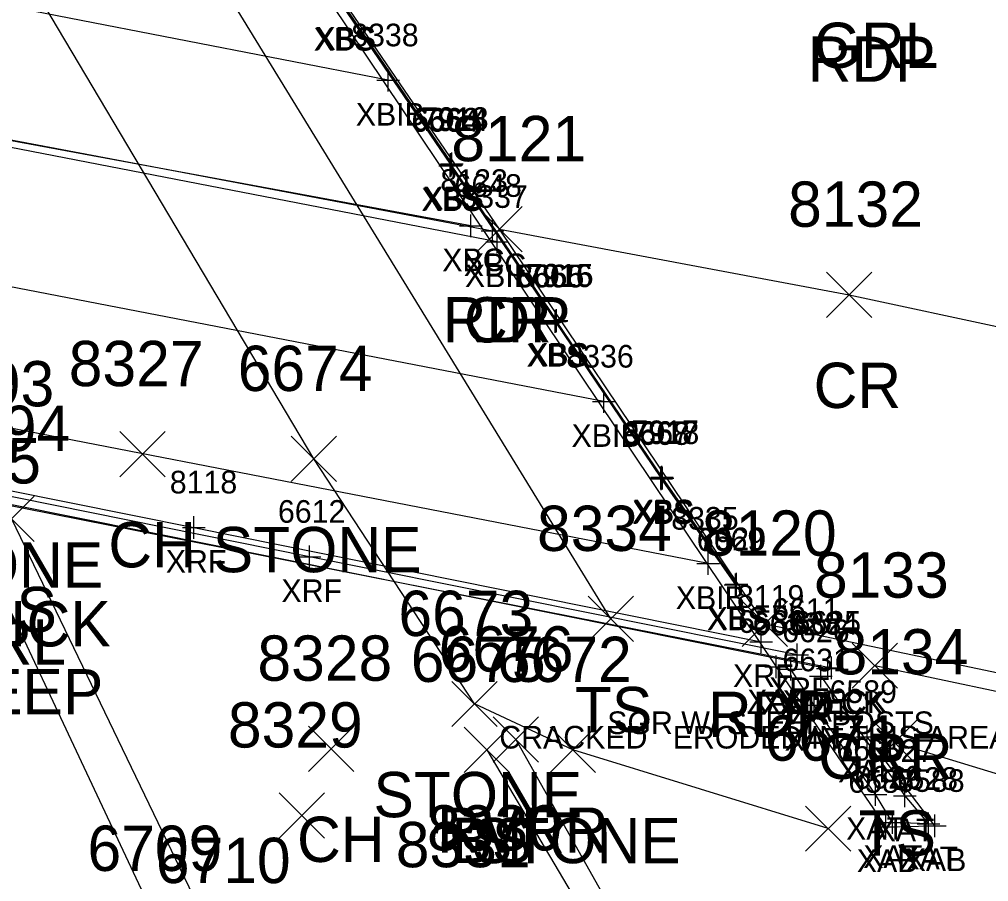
# Model space of a CAD drawing. Extents: x 1588028 to 1589597, y 137576 to 138176.
# Drawn here: x 1588943.52 to 1588986.3, y 137826.6 to 137864.66 of the extents above; entities that cross this region are included whole.
import ezdxf

# ---------------------------------------------------------------- set-up
doc = ezdxf.new("R2010")
doc.units = 0
for name, color, linetype in [('B_A', 7, 'Continuous'), ('B_C', 7, 'Continuous'), ('B_I', 7, 'Continuous'), ('B_TIC', 7, 'Continuous'), ('BB', 7, 'Continuous'), ('BELB', 7, 'Continuous'), ('BR', 7, 'Continuous'), ('BSE', 7, 'Continuous'), ('BSUBM', 7, 'Continuous'), ('L_A', 7, 'Continuous'), ('L_C', 7, 'Continuous'), ('L_I', 7, 'Continuous'), ('L_TIC', 7, 'Continuous'), ('LASF', 7, 'Continuous'), ('LAWE', 7, 'Continuous'), ('LELB', 7, 'Continuous'), ('P_A', 7, 'Continuous'), ('P_I', 7, 'Continuous'), ('P_TIC', 7, 'Continuous'), ('PET', 7, 'Continuous'), ('PRC', 7, 'Continuous'), ('R_A', 7, 'Continuous'), ('R_I', 7, 'Continuous'), ('R_TIC', 7, 'Continuous'), ('RGR', 7, 'Continuous')]:
    doc.layers.add(name, color=color, linetype=linetype)

msp = doc.modelspace()

# ---------------------------------------------------------------- linework, layer by layer
at = {"layer": 'B_TIC'}
for p, q in [((1588959.802, 137861.973), (1588959.878, 137861.973)), ((1588962.532, 137858.2), (1588962.608, 137858.2)), ((1588962.557, 137858.252), (1588962.633, 137858.252)), ((1588962.582, 137858.229), (1588962.657, 137858.229)), ((1588962.607, 137858.282), (1588962.683, 137858.282)), ((1588963.455, 137855.546), (1588963.53, 137855.546)), ((1588964.405, 137855.327), (1588964.481, 137855.327)), ((1588964.619, 137854.84), (1588964.694, 137854.84)), ((1588967.166, 137851.326), (1588967.241, 137851.326)), ((1588967.185, 137851.34), (1588967.261, 137851.34)), ((1588967.223, 137851.341), (1588967.299, 137851.341)), ((1588967.239, 137851.37), (1588967.314, 137851.37)), ((1588969.324, 137847.789), (1588969.4, 137847.789)), ((1588971.842, 137844.422), (1588971.917, 137844.422)), ((1588971.844, 137844.377), (1588971.92, 137844.377)), ((1588971.887, 137844.455), (1588971.963, 137844.455)), ((1588971.904, 137844.414), (1588971.98, 137844.414)), ((1588951.228, 137842.233), (1588951.304, 137842.233)), ((1588956.332, 137840.938), (1588956.408, 137840.938)), ((1588973.925, 137840.635), (1588974, 137840.635)), ((1588975.13, 137839.692), (1588975.205, 137839.692)), ((1588975.171, 137839.727), (1588975.246, 137839.727)), ((1588976.26, 137837.185), (1588976.336, 137837.185)), ((1588977.856, 137836.609), (1588977.931, 137836.609)), ((1588976.925, 137836.077), (1588977, 137836.077)), ((1588977.569, 137835.971), (1588977.645, 137835.971)), ((1588979.206, 137836), (1588979.281, 137836)), ((1588979.375, 137836.039), (1588979.45, 137836.039)), ((1588978.895, 137835.664), (1588978.97, 137835.664)), ((1588978.599, 137834.382), (1588978.675, 137834.382)), ((1588980.939, 137832.981), (1588981.014, 137832.981)), ((1588981.306, 137830.441), (1588981.382, 137830.441)), ((1588982.608, 137830.379), (1588982.683, 137830.379)), ((1588981.765, 137829.017), (1588981.841, 137829.017)), ((1588982.067, 137829.203), (1588982.142, 137829.203)), ((1588983.653, 137829.145), (1588983.729, 137829.145)), ((1588983.922, 137829.058), (1588983.998, 137829.058))]:
    msp.add_line(p, q, dxfattribs=at)
for points in [[(1588959.799, 137861.473), (1588959.799, 137862.473)], [(1588959.299, 137861.973), (1588960.299, 137861.973)], [(1588962.529, 137857.7), (1588962.529, 137858.7)], [(1588962.554, 137857.752), (1588962.554, 137858.752)], [(1588962.578, 137857.729), (1588962.578, 137858.729)], [(1588962.604, 137857.782), (1588962.604, 137858.782)], [(1588962.029, 137858.2), (1588963.029, 137858.2)], [(1588962.054, 137858.252), (1588963.054, 137858.252)], [(1588962.078, 137858.229), (1588963.078, 137858.229)], [(1588962.104, 137858.282), (1588963.104, 137858.282)], [(1588963.452, 137855.046), (1588963.452, 137856.046)], [(1588962.952, 137855.546), (1588963.952, 137855.546)], [(1588964.402, 137854.827), (1588964.402, 137855.827)], [(1588963.902, 137855.327), (1588964.902, 137855.327)], [(1588964.615, 137854.34), (1588964.615, 137855.34)], [(1588964.115, 137854.84), (1588965.115, 137854.84)], [(1588967.162, 137850.826), (1588967.162, 137851.826)], [(1588967.182, 137850.84), (1588967.182, 137851.84)], [(1588967.22, 137850.841), (1588967.22, 137851.841)], [(1588967.235, 137850.87), (1588967.235, 137851.87)], [(1588966.662, 137851.326), (1588967.662, 137851.326)], [(1588966.682, 137851.34), (1588967.682, 137851.34)], [(1588966.72, 137851.341), (1588967.72, 137851.341)], [(1588966.735, 137851.37), (1588967.735, 137851.37)], [(1588969.321, 137847.289), (1588969.321, 137848.289)], [(1588968.821, 137847.789), (1588969.821, 137847.789)], [(1588971.838, 137843.922), (1588971.838, 137844.922)], [(1588971.841, 137843.877), (1588971.841, 137844.877)], [(1588971.884, 137843.955), (1588971.884, 137844.955)], [(1588971.901, 137843.914), (1588971.901, 137844.914)], [(1588971.338, 137844.422), (1588972.338, 137844.422)], [(1588971.341, 137844.377), (1588972.341, 137844.377)], [(1588971.384, 137844.455), (1588972.384, 137844.455)], [(1588971.401, 137844.414), (1588972.401, 137844.414)], [(1588951.225, 137841.733), (1588951.225, 137842.733)], [(1588950.725, 137842.233), (1588951.725, 137842.233)], [(1588956.329, 137840.438), (1588956.329, 137841.438)], [(1588955.829, 137840.938), (1588956.829, 137840.938)], [(1588973.921, 137840.135), (1588973.921, 137841.135)], [(1588973.421, 137840.635), (1588974.421, 137840.635)], [(1588975.126, 137839.192), (1588975.126, 137840.192)], [(1588975.167, 137839.227), (1588975.167, 137840.227)], [(1588974.626, 137839.692), (1588975.626, 137839.692)], [(1588974.667, 137839.727), (1588975.667, 137839.727)], [(1588976.257, 137836.685), (1588976.257, 137837.685)], [(1588975.757, 137837.185), (1588976.757, 137837.185)], [(1588977.852, 137836.109), (1588977.852, 137837.109)], [(1588977.352, 137836.609), (1588978.352, 137836.609)], [(1588976.922, 137835.577), (1588976.922, 137836.577)], [(1588977.566, 137835.471), (1588977.566, 137836.471)], [(1588978.891, 137835.164), (1588978.891, 137836.164)], [(1588979.202, 137835.5), (1588979.202, 137836.5)], [(1588979.371, 137835.539), (1588979.371, 137836.539)], [(1588976.422, 137836.077), (1588977.422, 137836.077)], [(1588977.066, 137835.971), (1588978.066, 137835.971)], [(1588978.702, 137836), (1588979.702, 137836)], [(1588978.871, 137836.039), (1588979.871, 137836.039)], [(1588978.391, 137835.664), (1588979.391, 137835.664)], [(1588978.596, 137833.882), (1588978.596, 137834.882)], [(1588978.096, 137834.382), (1588979.096, 137834.382)], [(1588980.935, 137832.481), (1588980.935, 137833.481)], [(1588980.435, 137832.981), (1588981.435, 137832.981)], [(1588981.303, 137829.941), (1588981.303, 137830.941)], [(1588982.604, 137829.879), (1588982.604, 137830.879)], [(1588980.803, 137830.441), (1588981.803, 137830.441)], [(1588982.104, 137830.379), (1588983.104, 137830.379)], [(1588981.762, 137828.517), (1588981.762, 137829.517)], [(1588982.063, 137828.703), (1588982.063, 137829.703)], [(1588983.65, 137828.645), (1588983.65, 137829.645)], [(1588983.919, 137828.558), (1588983.919, 137829.558)], [(1588981.262, 137829.017), (1588982.262, 137829.017)], [(1588981.563, 137829.203), (1588982.563, 137829.203)], [(1588983.15, 137829.145), (1588984.15, 137829.145)], [(1588983.419, 137829.058), (1588984.419, 137829.058)]]:
    msp.add_lwpolyline(points, dxfattribs=at)
at = {"layer": 'BB'}
for points in [[(1588959.799, 137861.973), (1588912.85, 137871.124)], [(1588964.615, 137854.84), (1588917.658, 137863.951)], [(1588969.321, 137847.789), (1588922.415, 137856.857)], [(1588973.921, 137840.635), (1588927.197, 137849.709)]]:
    msp.add_lwpolyline(points, dxfattribs=at)
at = {"layer": 'BELB'}
for points in [[(1588917.303, 137864.223), (1588964.402, 137855.327)], [(1588963.452, 137855.546), (1588941.811, 137859.552), (1588919.044, 137863.553)], [(1588927.114, 137846.372), (1588979.371, 137836.039)], [(1588928.029, 137846.292), (1588979.202, 137836)]]:
    msp.add_lwpolyline(points, dxfattribs=at)
at = {"layer": 'BR'}
for points in [[(1588977.852, 137836.609), (1588956.329, 137840.938), (1588928.977, 137846.459)], [(1588929.192, 137846.665), (1588951.225, 137842.233), (1588976.257, 137837.185)]]:
    msp.add_lwpolyline(points, dxfattribs=at)
at = {"layer": 'BSE'}
for points in [[(1588954.828, 137869.716), (1588957.8, 137865.297), (1588957.774, 137865.279), (1588962.554, 137858.252), (1588962.529, 137858.2), (1588967.182, 137851.34), (1588967.162, 137851.326), (1588971.838, 137844.422), (1588971.841, 137844.377), (1588975.126, 137839.692)], [(1588954.879, 137869.737), (1588957.847, 137865.324), (1588957.824, 137865.308), (1588962.604, 137858.282), (1588962.578, 137858.229), (1588967.235, 137851.37), (1588967.22, 137851.341), (1588971.884, 137844.455), (1588971.901, 137844.414), (1588975.167, 137839.727)], [(1588975.167, 137839.727), (1588975.126, 137839.692)]]:
    msp.add_lwpolyline(points, dxfattribs=at)
at = {"layer": 'BSUBM'}
for points in [[(1588951.24, 137878.184), (1588950.245, 137880.086), (1588948.136, 137880.267), (1588950.99, 137874.773), (1588976.922, 137836.077), (1588981.762, 137829.017), (1588983.919, 137829.058), (1588980.935, 137832.981)], [(1588978.891, 137835.664), (1588982.604, 137830.379), (1588983.65, 137829.145), (1588982.063, 137829.203), (1588981.303, 137830.441), (1588978.596, 137834.382), (1588977.566, 137835.971)]]:
    msp.add_lwpolyline(points, dxfattribs=at)
at = {"layer": 'L_TIC'}
for points in [[(1588947.962, 137844.469), (1588949.962, 137846.469)], [(1588949.962, 137844.469), (1588947.962, 137846.469)], [(1588955.515, 137844.255), (1588957.515, 137846.255)], [(1588957.515, 137844.255), (1588955.515, 137846.255)], [(1588942.171, 137841.608), (1588944.171, 137843.608)], [(1588944.171, 137841.608), (1588942.171, 137843.608)], [(1588968.629, 137837.193), (1588970.629, 137839.193)], [(1588970.629, 137837.193), (1588968.629, 137839.193)], [(1588962.605, 137833.438), (1588964.605, 137835.438)], [(1588964.605, 137833.438), (1588962.605, 137835.438)], [(1588964.438, 137831.868), (1588966.438, 137833.868)], [(1588966.438, 137831.868), (1588964.438, 137833.868)], [(1588981.149, 137831.744), (1588983.149, 137833.744)], [(1588983.149, 137831.744), (1588981.149, 137833.744)], [(1588956.289, 137831.464), (1588958.289, 137833.464)], [(1588958.289, 137831.464), (1588956.289, 137833.464)], [(1588963.152, 137831.413), (1588965.152, 137833.413)], [(1588965.152, 137831.413), (1588963.152, 137833.413)], [(1588966.953, 137831.409), (1588968.953, 137833.409)], [(1588968.953, 137831.409), (1588966.953, 137833.409)], [(1588954.994, 137828.515), (1588956.994, 137830.515)], [(1588956.994, 137828.515), (1588954.994, 137830.515)], [(1588978.213, 137827.934), (1588980.213, 137829.934)], [(1588980.213, 137827.934), (1588978.213, 137829.934)]]:
    msp.add_lwpolyline(points, dxfattribs=at)
at = {"layer": 'LASF'}
for points in [[(1588956.515, 137845.255), (1588938.518, 137875.567)], [(1588979.213, 137828.934), (1588967.953, 137832.409), (1588963.605, 137834.438), (1588956.515, 137845.255)]]:
    msp.add_lwpolyline(points, dxfattribs=at)
at = {"layer": 'LAWE'}
for points in [[(1588941.88, 137841.174), (1588949.924, 137824.068), (1588963.725, 137811.706), (1588978.436, 137804.59)], [(1588965.438, 137832.868), (1588973.43, 137818.618), (1588989.605, 137813.178), (1589022.835, 137804.122), (1589064.642, 137785.889), (1589085.422, 137779.689), (1589097.716, 137781.174), (1589112.628, 137775.029), (1589131.452, 137759.723), (1589147.925, 137745.25), (1589161.346, 137734.825)]]:
    msp.add_lwpolyline(points, dxfattribs=at)
at = {"layer": 'LELB'}
for points in [[(1588969.629, 137838.193), (1588948.788, 137872.187)], [(1588943.171, 137842.608), (1588952.372, 137823.531), (1588964.918, 137812.896), (1588979.766, 137805.361)], [(1588982.149, 137832.744), (1589014.45, 137822.897), (1589047.332, 137817.07), (1589086.545, 137806.425), (1589114.036, 137794.197), (1589138.041, 137783.394), (1589164.043, 137781.215)], [(1588964.152, 137832.413), (1588972.642, 137818.049), (1588989.972, 137811.45)]]:
    msp.add_lwpolyline(points, dxfattribs=at)
at = {"layer": 'P_TIC'}
for points in [[(1588963.714, 137854.4), (1588965.714, 137856.4)], [(1588965.714, 137854.4), (1588963.714, 137856.4)], [(1588963.714, 137854.4), (1588965.714, 137856.4)], [(1588965.714, 137854.4), (1588963.714, 137856.4)], [(1588979.143, 137851.505), (1588981.143, 137853.505)], [(1588981.143, 137851.505), (1588979.143, 137853.505)], [(1588975.423, 137836.983), (1588977.423, 137838.983)], [(1588977.423, 137836.983), (1588975.423, 137838.983)], [(1588975.423, 137836.983), (1588977.423, 137838.983)], [(1588977.423, 137836.983), (1588975.423, 137838.983)]]:
    msp.add_lwpolyline(points, dxfattribs=at)
at = {"layer": 'PET'}
for points in [[(1588976.423, 137837.983), (1588964.714, 137855.4), (1588953.737, 137871.461), (1588980.824, 137866.908), (1589021.21, 137859.548), (1589054.577, 137852.925), (1589087.364, 137843.769), (1589127.637, 137831.447), (1589150.053, 137824.373), (1589196.141, 137808.721), (1589243.873, 137790.956), (1589276.872, 137778.078), (1589322.252, 137759.621), (1589367.819, 137740.822), (1589401.867, 137726.111), (1589432.806, 137712.852), (1589459.757, 137701.463)], [(1588976.423, 137837.983), (1589015.381, 137829.765), (1589047.772, 137821.866), (1589087.616, 137811.066), (1589117.339, 137801.667), (1589165.817, 137785.247), (1589185.233, 137778.165), (1589232.279, 137760.805), (1589265.319, 137747.808), (1589310.312, 137729.828), (1589359.625, 137709.23), (1589389.546, 137696.801), (1589422.315, 137682.688), (1589446.912, 137672.539)]]:
    msp.add_lwpolyline(points, dxfattribs=at)
at = {"layer": 'PRC'}
msp.add_lwpolyline([(1588964.714, 137855.4), (1588980.143, 137852.505), (1589018.187, 137844.354), (1589051.571, 137836.274), (1589092.272, 137825.066), (1589122.683, 137816.233), (1589170.698, 137800.292), (1589190.716, 137793.381), (1589238.444, 137775.617), (1589271.315, 137762.403), (1589315.937, 137744.353), (1589366.219, 137723.583), (1589395.713, 137710.875), (1589428.179, 137697.421), (1589453.327, 137686.423)], dxfattribs=at)
at = {"layer": 'R_TIC'}
for points in [[(1588980.284, 137835.13), (1588982.284, 137837.13)], [(1588982.284, 137835.13), (1588980.284, 137837.13)]]:
    msp.add_lwpolyline(points, dxfattribs=at)
at = {"layer": 'RGR'}
msp.add_lwpolyline([(1588981.284, 137836.13), (1589015.234, 137828.949), (1589047.722, 137821.351), (1589087.452, 137810.415), (1589116.476, 137799.61), (1589136.35, 137790.835)], dxfattribs=at)

# ---------------------------------------------------------------- texts
at = {"layer": 'B_A'}
for s, p in [('XBS', (1588956.514, 137863.279)), ('XBS', (1588956.54, 137863.297)), ('XBS', (1588956.564, 137863.308)), ('XBS', (1588956.587, 137863.324)), ('XBIB', (1588958.37, 137859.973)), ('XBS', (1588961.269, 137856.2)), ('XBS', (1588961.294, 137856.252)), ('XBS', (1588961.318, 137856.229)), ('XBS', (1588961.344, 137856.282)), ('XBC', (1588962.188, 137853.546)), ('XBC', (1588963.138, 137853.327)), ('XBIB', (1588963.186, 137852.84)), ('XBS', (1588965.902, 137849.326)), ('XBS', (1588965.922, 137849.34)), ('XBS', (1588965.96, 137849.341)), ('XBS', (1588965.975, 137849.37)), ('XBIB', (1588967.892, 137845.789)), ('XBS', (1588970.578, 137842.422)), ('XBS', (1588970.624, 137842.455)), ('XBS', (1588970.641, 137842.414)), ('XBS', (1588970.581, 137842.377)), ('XRF', (1588949.985, 137840.233)), ('XRF', (1588955.089, 137838.938)), ('XBIB', (1588972.492, 137838.635)), ('XBS', (1588973.908, 137837.727)), ('XBS', (1588973.866, 137837.692)), ('XRF', (1588975.017, 137835.185)), ('XRF', (1588976.612, 137834.609)), ('XAB', (1588975.642, 137834.077)), ('XAT', (1588976.27, 137833.971)), ('XDECK', (1588977.045, 137834)), ('XDECK', (1588977.214, 137834.039)), ('XAT', (1588977.596, 137833.664)), ('XAT', (1588977.301, 137832.382)), ('XAB', (1588979.656, 137830.981)), ('XAT', (1588980.008, 137828.441)), ('XAT', (1588981.309, 137828.379)), ('XAT', (1588980.768, 137827.203)), ('XAT', (1588982.355, 137827.145)), ('XAB', (1588982.639, 137827.058)), ('XAB', (1588980.482, 137827.017))]:
    msp.add_text(s, height=1, dxfattribs=at).set_placement(p)
at = {"layer": 'B_C'}
for s, p in [('SGR W/ STEEL POSTS', (1588969.466, 137833.109)), ('CRACKED   ERODED IN THIS AREA', (1588964.703, 137832.471))]:
    msp.add_text(s, height=1, dxfattribs=at).set_placement(p)
at = {"layer": 'B_I'}
for s, p in [('8338', (1588958.169, 137863.473)), ('6664', (1588960.828, 137859.7)), ('6663', (1588960.853, 137859.752)), ('7914', (1588961.232, 137859.729)), ('7913', (1588961.257, 137859.782)), ('8123', (1588962.105, 137857.046)), ('6648', (1588962.724, 137856.827)), ('8337', (1588962.985, 137856.34)), ('6666', (1588965.434, 137852.826)), ('6665', (1588965.481, 137852.84)), ('7916', (1588965.846, 137852.841)), ('7915', (1588965.889, 137852.87)), ('8336', (1588967.663, 137849.289)), ('6667', (1588970.138, 137845.922)), ('6668', (1588970.14, 137845.877)), ('7917', (1588970.537, 137845.955)), ('7918', (1588970.554, 137845.914)), ('8118', (1588950.162, 137843.733)), ('6612', (1588954.935, 137842.438)), ('8335', (1588972.291, 137842.135)), ('6669', (1588973.421, 137841.192)), ('7920', (1588973.494, 137841.227)), ('8119', (1588975.19, 137838.685)), ('6611', (1588976.742, 137838.109)), ('6586', (1588975.24, 137837.577)), ('6632', (1588975.889, 137837.471)), ('8384', (1588977.572, 137837.5)), ('6625', (1588977.694, 137837.539)), ('6626', (1588977.187, 137837.164)), ('6631', (1588977.202, 137835.882)), ('6589', (1588979.278, 137834.481)), ('6630', (1588979.582, 137831.941)), ('6627', (1588980.927, 137831.879)), ('6587', (1588980.108, 137830.517)), ('6629', (1588980.382, 137830.703)), ('6628', (1588981.973, 137830.645)), ('6588', (1588982.265, 137830.558))]:
    msp.add_text(s, height=1, dxfattribs=at).set_placement(p)
at = {"layer": 'L_A'}
for s, p in [('CH', (1588947.45, 137840.469)), ('STONE', (1588952.059, 137840.255)), ('STONE', (1588938.012, 137839.578)), ('BS', (1588941.612, 137837.608)), ('RVRL', (1588938.447, 137836.174)), ('TS', (1588968.039, 137833.193)), ('STONE', (1588959.149, 137829.438)), ('RVRR', (1588961.95, 137827.868)), ('TS', (1588980.559, 137827.744)), ('CH', (1588955.777, 137827.464)), ('BS', (1588962.593, 137827.413)), ('STONE', (1588963.497, 137827.409))]:
    msp.add_text(s, height=2, dxfattribs=at).set_placement(p)
at = {"layer": 'L_C'}
for s, p in [('BRIDGE DECK IS 0.67 THICK', (1588911.143, 137836.978)), ('BRIDGE SEAT IS 1.28 DEEP', (1588912.001, 137833.978))]:
    msp.add_text(s, height=2, dxfattribs=at).set_placement(p)
at = {"layer": 'L_I'}
for s, p in [('8327', (1588945.702, 137848.469)), ('6674', (1588953.161, 137848.255)), ('6693', (1588939.114, 137847.578)), ('6694', (1588939.817, 137845.608)), ('6695', (1588938.526, 137844.174)), ('8334', (1588966.369, 137841.193)), ('6673', (1588960.251, 137837.438)), ('6676', (1588962.029, 137835.868)), ('8328', (1588954.029, 137835.464)), ('6675', (1588960.798, 137835.413)), ('6672', (1588964.599, 137835.409)), ('8134', (1588979.456, 137835.744)), ('8329', (1588952.726, 137832.515)), ('6671', (1588976.425, 137831.934)), ('8330', (1588961.513, 137827.969)), ('6709', (1588946.53, 137827.068)), ('8331', (1588960.135, 137827.231)), ('6710', (1588949.545, 137826.531))]:
    msp.add_text(s, height=2, dxfattribs=at).set_placement(p)
at = {"layer": 'P_A'}
for s, p in [('RDP', (1588978.312, 137861.908)), ('CR', (1588963.147, 137850.4)), ('RDP', (1588962.203, 137850.4)), ('CR', (1588978.576, 137847.505)), ('RDP', (1588973.911, 137832.983)), ('RDP', (1588973.911, 137832.983))]:
    msp.add_text(s, height=2, dxfattribs=at).set_placement(p)
at = {"layer": 'P_I'}
for s, p in [('8121', (1588962.588, 137858.4)), ('8121', (1588962.588, 137858.4)), ('8132', (1588977.45, 137855.505)), ('8120', (1588973.643, 137840.983)), ('8120', (1588973.643, 137840.983))]:
    msp.add_text(s, height=2, dxfattribs=at).set_placement(p)
at = {"layer": 'R_A'}
for s, p in [('GRL', (1588978.587, 137862.516)), ('GRR', (1588978.772, 137831.13))]:
    msp.add_text(s, height=2, dxfattribs=at).set_placement(p)
at = {"layer": 'R_I'}
msp.add_text('8133', height=2, dxfattribs=at).set_placement((1588978.591, 137839.13))

doc.saveas('drawing.dxf')
